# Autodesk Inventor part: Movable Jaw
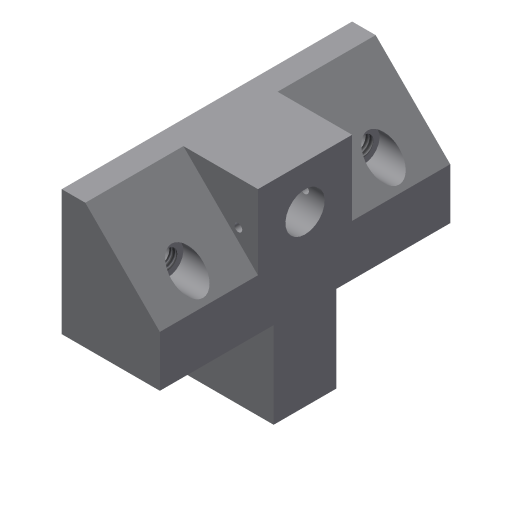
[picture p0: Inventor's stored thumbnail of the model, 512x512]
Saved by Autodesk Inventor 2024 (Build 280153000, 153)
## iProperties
Shininess: 77.0
Length Units: 11269
Angle Units: 11279
Time Units: 11290
Mass Units: 11283
Length Display Precision: 3
Angle Display Precision: 2
Created: 2002-02
Part Number: Movable Jaw
Document SubType Name: Modeling
Designer: ***
Density: 1 g/cm^3
Material: Generic
Mass: 56.5588 g
Surface Area: 124.299 cm^2
Volume: 56.5588 cm^3
Appearance: Default
Density: 0.0
Volumn: 0.0
Area: 0.0
PropertySet Name: Model Information
Control State: 0
Master: False
Checked Out: False
Author: ***
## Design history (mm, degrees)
sketch "Sketch2"
  geometry: L1 (2.39, 41.509)-(2.39, 9.509); L2 (2.39, 9.509)-(-22.61, 9.509); L3 (-22.61, 9.509)-(-22.61, 22.509); L4 (-22.61, 22.509)-(-3.61, 41.509); L5 (-3.61, 41.509)-(2.39, 41.509)
  constraints: 10 end point, 2 parallel, 1 perpendicular, 1 vertical
  dimensions: "d0" = 25 distance of L1.end L2.end; "d2" = 13 distance of L2.end L3.end; "d3" = 32 distance between parallel lines of L5 L2; "d4" = 6 distance of L4.end L1.start
extrude "Extrusion1" new body sketch "Sketch2" stored distance "d5" = 74; taper "d6" = 0 deg
sketch "Sketch3"
  geometry: L1 (-19, 25)-(11, 25); L2 (11, 25)-(11, 49); L3 (11, 49)-(-19, 49); L4 (-19, 49)-(-19, 25); L5 (0, 0)-(13, 0) reference; L6 (-19, 74)-(-19, 0) reference; L7 (11.924, 29)-(35, 29); L8 (35, 29)-(35, 45); L9 (35, 45)-(11.924, 45); L10 (11.924, 45)-(11.924, 29); L11 (13, 74)-(13, 0) reference
  constraints: 16 end point, 4 parallel, 2 horizontal, 2 perpendicular, 1 collinear
  dimensions: "d7" = 24 distance of L3.end L1.start; "d8" = 30 distance of L1.start L1.end; "d9" = 25 distance between parallel lines of L5 L1; "d10" = 16 distance of L7.end L8.end; "d11" = 4 distance between parallel lines of L3 L9; "d12" = 22 distance between parallel lines of L11 L8
extrude "Extrusion2" join sketch "Sketch3" distance "d13" = 25; taper "d14" = 0 deg
sketch "Sketch4"
  geometry: L1 (-19, -25)-(-19, -49) reference; L2 (-19, -49)-(0, -49) reference; 1 further point
  dimensions: "d15" = 11 distance from line of L1 point (-8, -37); "d16" = 12 distance from line of L2 point (-8, -37)
hole "Hole1" sketch "Sketch4" diameter "d17" = 10; stored, may be unused: countersink angle "d21" = 82 deg, drill point angle "d23" = 0 deg; dims "d18" = 6, "d19" = 4, "d20" = 2, "d22" = 13
sketch "Sketch5"
  geometry: L1 (-19, -49)-(-19, -74) reference; L2 (0, -74)-(13, -74) reference; 1 further point
  dimensions: "d24" = 14 distance from line of L1 point (-5, -62); "d25" = 12 distance from line of L2 point (-5, -62)
hole "Hole2" sketch "Sketch5" diameter "d26" = 4.917; stored, may be unused: countersink angle "d30" = 82 deg, drill point angle "d32" = 0 deg; dims "d27" = 12, "d28" = 8, "d29" = 10, "d31" = 17.1
mirror "Mirror1"
sketch "Sketch6"
  geometry: L1 (0, 19)-(0, 0) reference; 1 further point
  dimensions: "d33" = 5 distance from line of L1 point (-5, 8); "d34" = 11 vertical distance of L1.start point (-5, 8)
hole "Hole3" sketch "Sketch6" diameter "d35" = 2; stored, may be unused: countersink angle "d39" = 82 deg, drill point angle "d41" = 0 deg; dims "d36" = 6, "d37" = 8, "d38" = 10, "d40" = 13
body "Solid1"
